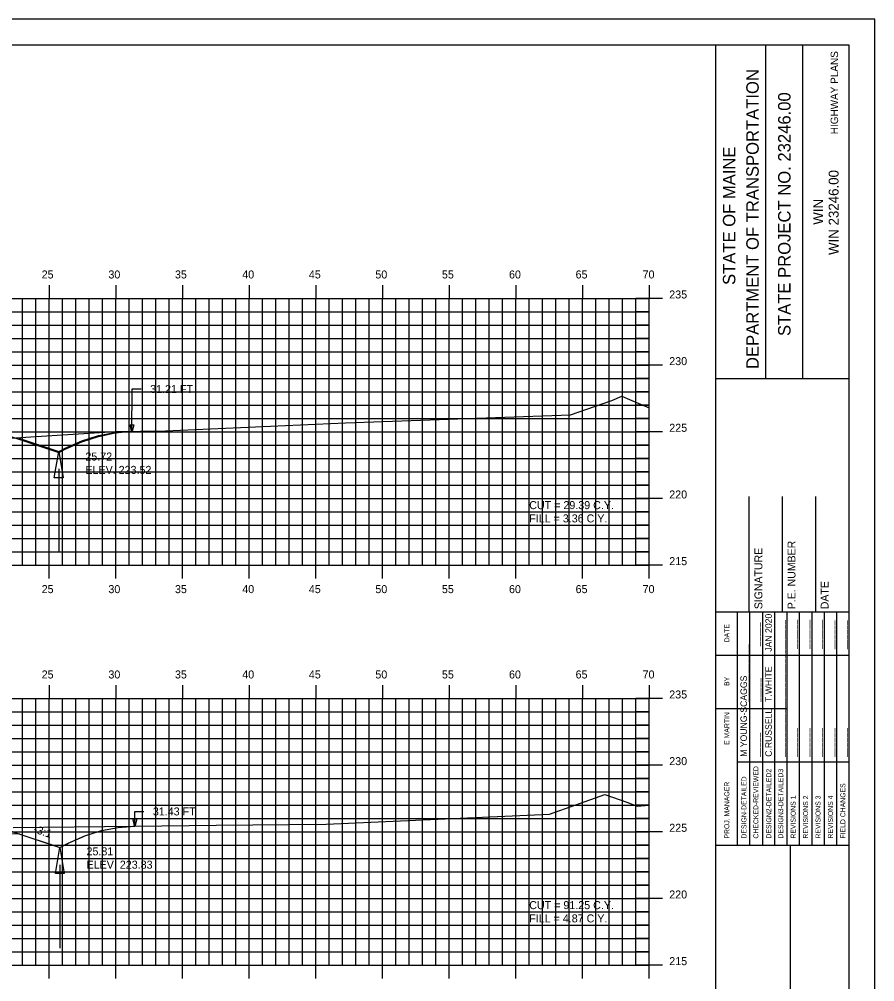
# Model space of a CAD drawing. Extents: x 1137433 to 1137603, y 608981 to 609091.
# Drawn here: x 1137538.4 to 1137602.6, y 609019.1 to 609091.3 of the extents above; entities that cross this region are included whole.
import ezdxf

# ---------------------------------------------------------------- set-up
doc = ezdxf.new("R2010")
doc.units = 0
for name, color, linetype in [('ANNOTATION', 7, 'Continuous'), ('BORDER', 7, 'Continuous'), ('D_Drainage_Ditch_Line', 7, 'Continuous'), ('D_Roadway_SlopeLines', 7, 'Continuous'), ('D_Roadway_SubGrade', 7, 'Continuous'), ('D_Text_Standard', 7, 'Continuous'), ('H_V ANNOTATION', 7, 'Continuous'), ('HIGHWAY_TITLE', 7, 'Continuous'), ('MAJOR', 7, 'Continuous'), ('MINOR', 7, 'Continuous'), ('PLOT BOUNDARY', 7, 'Continuous'), ('S_Roadway_Centerline', 7, 'Continuous')]:
    doc.layers.add(name, color=color, linetype=linetype)

msp = doc.modelspace()

# ---------------------------------------------------------------- linework, layer by layer
for points in [[(1137498.181, 609061.117), (1137500.653, 609061.475), (1137504.653, 609061.635), (1137515.653, 609062.075), (1137526.653, 609062.515), (1137530.653, 609062.355), (1137538.376, 609059.781), (1137541.376, 609058.781), (1137541.866, 609059.026), (1137543.116, 609059.579), (1137544.366, 609059.988), (1137545.616, 609060.252), (1137546.866, 609060.373)], [(1137537.514, 609030.485), (1137538.461, 609030.169), (1137541.099, 609029.29), (1137541.461, 609029.169), (1137542.009, 609029.443), (1137542.087, 609029.482), (1137543.187, 609029.965), (1137543.337, 609030.031), (1137544.437, 609030.379), (1137544.587, 609030.426), (1137545.687, 609030.639), (1137545.837, 609030.668), (1137546.937, 609030.747), (1137547.087, 609030.758)]]:
    msp.add_lwpolyline(points)
at = {"layer": 'BORDER'}
for p, q in [((1137590.653, 608984.335), (1137590.653, 609089.335)), ((1137594.382, 609064.332), (1137594.382, 609089.332)), ((1137597.177, 609064.332), (1137597.177, 609089.332)), ((1137590.654, 609064.329), (1137600.653, 609064.329)), ((1137593.153, 609046.838), (1137593.153, 609055.485)), ((1137595.653, 609046.838), (1137595.653, 609055.485)), ((1137598.153, 609046.838), (1137598.153, 609055.485)), ((1137590.653, 609046.838), (1137600.653, 609046.838)), ((1137590.653, 609029.338), (1137600.653, 609029.338)), ((1137596.244, 608994.338), (1137596.244, 609029.338))]:
    msp.add_line(p, q, dxfattribs=at)
msp.add_lwpolyline([(1137440.653, 608984.335), (1137600.653, 608984.335), (1137600.653, 609089.335), (1137440.653, 609089.335)], close=True, dxfattribs=at)
for points in [[(1137592.268, 609043.588), (1137592.268, 609046.838)], [(1137593.201, 609029.341), (1137593.201, 609046.838)], [(1137594.132, 609046.838), (1137594.132, 609029.341)], [(1137595.064, 609029.341), (1137595.064, 609046.838)], [(1137595.996, 609029.341), (1137595.996, 609046.838)], [(1137596.927, 609029.341), (1137596.927, 609046.838)], [(1137597.859, 609029.341), (1137597.859, 609046.838)], [(1137598.791, 609029.341), (1137598.791, 609046.838)], [(1137599.722, 609029.341), (1137599.722, 609046.838)], [(1137592.269, 609029.341), (1137592.269, 609046.132)], [(1137590.653, 609043.588), (1137600.653, 609043.588)], [(1137590.653, 609039.588), (1137592.269, 609039.588)], [(1137592.268, 609039.588), (1137595.995, 609039.588)], [(1137592.268, 609035.588), (1137600.653, 609035.588)]]:
    msp.add_lwpolyline(points, dxfattribs=at)
at = {"layer": 'D_Drainage_Ditch_Line'}
for p, q in [((1137541.376, 609057.549), (1137541.376, 609051.305)), ((1137541.461, 609027.857), (1137541.461, 609021.613))]:
    msp.add_line(p, q, dxfattribs=at)
for points in [[(1137541.704, 609056.892), (1137541.048, 609056.892), (1137541.376, 609058.861)], [(1137541.789, 609027.201), (1137541.133, 609027.201), (1137541.461, 609029.169)]]:
    msp.add_lwpolyline(points, close=True, dxfattribs=at)
at = {"layer": 'D_Roadway_SlopeLines'}
for points in [[(1137541.376, 609058.861), (1137541.866, 609059.106), (1137543.116, 609059.659), (1137544.366, 609060.068), (1137545.618, 609060.284), (1137546.863, 609060.373)], [(1137538.376, 609059.861), (1137541.376, 609058.861)], [(1137541.461, 609029.169), (1137542.087, 609029.482), (1137543.337, 609030.031), (1137544.587, 609030.426), (1137545.837, 609030.668), (1137547.087, 609030.758)], [(1137538.461, 609030.169), (1137541.461, 609029.169)]]:
    msp.add_lwpolyline(points, dxfattribs=at)
at = {"layer": 'D_Roadway_SubGrade'}
msp.add_lwpolyline([(1137526.653, 609032.489), (1137526.653, 609032.655), (1137530.653, 609032.522), (1137530.653, 609032.772), (1137530.653, 609032.772), (1137538.461, 609030.169), (1137526.653, 609030.405)], close=True, dxfattribs=at)
at = {"layer": 'D_Text_Standard'}
for points in [[(1137546.866, 609060.276), (1137546.874, 609063.546), (1137547.554, 609063.546)], [(1137547.087, 609030.732), (1137547.075, 609031.863), (1137547.755, 609031.863)]]:
    msp.add_lwpolyline(points, dxfattribs=at)
for points in [[(1137546.866, 609060.276), (1137546.722, 609060.858), (1137547.013, 609060.857)], [(1137547.087, 609030.732), (1137546.935, 609031.313), (1137547.226, 609031.316)]]:
    msp.add_lwpolyline(points, close=True, dxfattribs=at)
at = {"layer": 'MAJOR'}
for p, q in [((1137540.653, 609071.337), (1137540.653, 609070.335)), ((1137545.653, 609071.337), (1137545.653, 609070.335)), ((1137550.653, 609071.337), (1137550.653, 609070.335)), ((1137555.653, 609071.337), (1137555.653, 609070.335)), ((1137560.653, 609071.337), (1137560.653, 609070.335)), ((1137565.653, 609071.337), (1137565.653, 609070.335)), ((1137570.653, 609071.337), (1137570.653, 609070.335)), ((1137575.653, 609071.337), (1137575.653, 609070.335)), ((1137580.653, 609071.337), (1137580.653, 609070.335)), ((1137585.653, 609071.337), (1137585.653, 609070.335)), ((1137445.653, 609070.335), (1137585.653, 609070.335)), ((1137445.653, 609070.335), (1137585.653, 609070.335)), ((1137540.653, 609050.335), (1137540.653, 609070.335)), ((1137545.653, 609050.335), (1137545.653, 609070.335)), ((1137550.653, 609050.335), (1137550.653, 609070.335)), ((1137555.653, 609050.335), (1137555.653, 609070.335)), ((1137560.653, 609050.335), (1137560.653, 609070.335)), ((1137565.653, 609050.335), (1137565.653, 609070.335)), ((1137570.653, 609050.335), (1137570.653, 609070.335)), ((1137575.653, 609050.335), (1137575.653, 609070.335)), ((1137580.653, 609050.335), (1137580.653, 609070.335)), ((1137586.655, 609070.335), (1137584.651, 609070.335)), ((1137585.653, 609050.335), (1137585.653, 609070.335)), ((1137585.653, 609050.335), (1137585.653, 609070.335)), ((1137445.653, 609065.335), (1137585.653, 609065.335)), ((1137586.655, 609065.335), (1137584.651, 609065.335)), ((1137445.653, 609060.335), (1137585.653, 609060.335)), ((1137586.655, 609060.335), (1137584.651, 609060.335)), ((1137445.653, 609055.335), (1137585.653, 609055.335)), ((1137586.655, 609055.335), (1137584.651, 609055.335)), ((1137445.653, 609050.335), (1137585.653, 609050.335)), ((1137445.653, 609050.335), (1137585.653, 609050.335)), ((1137540.653, 609049.333), (1137540.653, 609050.335)), ((1137545.653, 609049.333), (1137545.653, 609050.335)), ((1137550.653, 609049.333), (1137550.653, 609050.335)), ((1137555.653, 609049.333), (1137555.653, 609050.335)), ((1137560.653, 609049.333), (1137560.653, 609050.335)), ((1137565.653, 609049.333), (1137565.653, 609050.335)), ((1137570.653, 609049.333), (1137570.653, 609050.335)), ((1137575.653, 609049.333), (1137575.653, 609050.335)), ((1137580.653, 609049.333), (1137580.653, 609050.335)), ((1137586.655, 609050.335), (1137584.651, 609050.335)), ((1137585.653, 609049.333), (1137585.653, 609050.335)), ((1137540.653, 609041.337), (1137540.653, 609040.335)), ((1137545.653, 609041.337), (1137545.653, 609040.335)), ((1137550.653, 609041.337), (1137550.653, 609040.335)), ((1137555.653, 609041.337), (1137555.653, 609040.335)), ((1137560.653, 609041.337), (1137560.653, 609040.335)), ((1137565.653, 609041.337), (1137565.653, 609040.335)), ((1137570.653, 609041.337), (1137570.653, 609040.335)), ((1137575.653, 609041.337), (1137575.653, 609040.335)), ((1137580.653, 609041.337), (1137580.653, 609040.335)), ((1137585.653, 609041.337), (1137585.653, 609040.335)), ((1137445.653, 609040.335), (1137585.653, 609040.335)), ((1137445.653, 609040.335), (1137585.653, 609040.335)), ((1137540.653, 609020.335), (1137540.653, 609040.335)), ((1137545.653, 609020.335), (1137545.653, 609040.335)), ((1137550.653, 609020.335), (1137550.653, 609040.335)), ((1137555.653, 609020.335), (1137555.653, 609040.335)), ((1137560.653, 609020.335), (1137560.653, 609040.335)), ((1137565.653, 609020.335), (1137565.653, 609040.335)), ((1137570.653, 609020.335), (1137570.653, 609040.335)), ((1137575.653, 609020.335), (1137575.653, 609040.335)), ((1137580.653, 609020.335), (1137580.653, 609040.335)), ((1137586.655, 609040.335), (1137584.651, 609040.335)), ((1137585.653, 609020.335), (1137585.653, 609040.335)), ((1137585.653, 609020.335), (1137585.653, 609040.335)), ((1137445.653, 609035.335), (1137585.653, 609035.335)), ((1137586.655, 609035.335), (1137584.651, 609035.335)), ((1137445.653, 609030.335), (1137585.653, 609030.335)), ((1137586.655, 609030.335), (1137584.651, 609030.335)), ((1137445.653, 609025.335), (1137585.653, 609025.335)), ((1137586.655, 609025.335), (1137584.651, 609025.335)), ((1137445.653, 609020.335), (1137585.653, 609020.335)), ((1137445.653, 609020.335), (1137585.653, 609020.335)), ((1137540.653, 609019.333), (1137540.653, 609020.335)), ((1137545.653, 609019.333), (1137545.653, 609020.335)), ((1137550.653, 609019.333), (1137550.653, 609020.335)), ((1137555.653, 609019.333), (1137555.653, 609020.335)), ((1137560.653, 609019.333), (1137560.653, 609020.335)), ((1137565.653, 609019.333), (1137565.653, 609020.335)), ((1137570.653, 609019.333), (1137570.653, 609020.335)), ((1137575.653, 609019.333), (1137575.653, 609020.335)), ((1137580.653, 609019.333), (1137580.653, 609020.335)), ((1137586.655, 609020.335), (1137584.651, 609020.335)), ((1137585.653, 609019.333), (1137585.653, 609020.335))]:
    msp.add_line(p, q, dxfattribs=at)
at = {"layer": 'MINOR'}
for p, q in [((1137538.653, 609050.335), (1137538.653, 609070.335)), ((1137539.653, 609050.335), (1137539.653, 609070.335)), ((1137541.653, 609050.335), (1137541.653, 609070.335)), ((1137542.653, 609050.335), (1137542.653, 609070.335)), ((1137543.653, 609050.335), (1137543.653, 609070.335)), ((1137544.653, 609050.335), (1137544.653, 609070.335)), ((1137546.653, 609050.335), (1137546.653, 609070.335)), ((1137547.653, 609050.335), (1137547.653, 609070.335)), ((1137548.653, 609050.335), (1137548.653, 609070.335)), ((1137549.653, 609050.335), (1137549.653, 609070.335)), ((1137551.653, 609050.335), (1137551.653, 609070.335)), ((1137552.653, 609050.335), (1137552.653, 609070.335)), ((1137553.653, 609050.335), (1137553.653, 609070.335)), ((1137554.653, 609050.335), (1137554.653, 609070.335)), ((1137556.653, 609050.335), (1137556.653, 609070.335)), ((1137557.653, 609050.335), (1137557.653, 609070.335)), ((1137558.653, 609050.335), (1137558.653, 609070.335)), ((1137559.653, 609050.335), (1137559.653, 609070.335)), ((1137561.653, 609050.335), (1137561.653, 609070.335)), ((1137562.653, 609050.335), (1137562.653, 609070.335)), ((1137563.653, 609050.335), (1137563.653, 609070.335)), ((1137564.653, 609050.335), (1137564.653, 609070.335)), ((1137566.653, 609050.335), (1137566.653, 609070.335)), ((1137567.653, 609050.335), (1137567.653, 609070.335)), ((1137568.653, 609050.335), (1137568.653, 609070.335)), ((1137569.653, 609050.335), (1137569.653, 609070.335)), ((1137571.653, 609050.335), (1137571.653, 609070.335)), ((1137572.653, 609050.335), (1137572.653, 609070.335)), ((1137573.653, 609050.335), (1137573.653, 609070.335)), ((1137574.653, 609050.335), (1137574.653, 609070.335)), ((1137576.653, 609050.335), (1137576.653, 609070.335)), ((1137577.653, 609050.335), (1137577.653, 609070.335)), ((1137578.653, 609050.335), (1137578.653, 609070.335)), ((1137579.653, 609050.335), (1137579.653, 609070.335)), ((1137581.653, 609050.335), (1137581.653, 609070.335)), ((1137582.653, 609050.335), (1137582.653, 609070.335)), ((1137583.653, 609050.335), (1137583.653, 609070.335)), ((1137584.653, 609050.335), (1137584.653, 609070.335)), ((1137445.653, 609069.335), (1137585.653, 609069.335)), ((1137585.653, 609069.335), (1137584.651, 609069.335)), ((1137445.653, 609068.335), (1137585.653, 609068.335)), ((1137585.653, 609068.335), (1137584.651, 609068.335)), ((1137445.653, 609067.335), (1137585.653, 609067.335)), ((1137585.653, 609067.335), (1137584.651, 609067.335)), ((1137445.653, 609066.335), (1137585.653, 609066.335)), ((1137585.653, 609066.335), (1137584.651, 609066.335)), ((1137445.653, 609064.335), (1137585.653, 609064.335)), ((1137585.653, 609064.335), (1137584.651, 609064.335)), ((1137445.653, 609063.335), (1137585.653, 609063.335)), ((1137585.653, 609063.335), (1137584.651, 609063.335)), ((1137445.653, 609062.335), (1137585.653, 609062.335)), ((1137585.653, 609062.335), (1137584.651, 609062.335)), ((1137445.653, 609061.335), (1137585.653, 609061.335)), ((1137585.653, 609061.335), (1137584.651, 609061.335)), ((1137445.653, 609059.335), (1137585.653, 609059.335)), ((1137585.653, 609059.335), (1137584.651, 609059.335)), ((1137445.653, 609058.335), (1137585.653, 609058.335)), ((1137585.653, 609058.335), (1137584.651, 609058.335)), ((1137445.653, 609057.335), (1137585.653, 609057.335)), ((1137585.653, 609057.335), (1137584.651, 609057.335)), ((1137445.653, 609056.335), (1137585.653, 609056.335)), ((1137585.653, 609056.335), (1137584.651, 609056.335)), ((1137445.653, 609054.335), (1137585.653, 609054.335)), ((1137585.653, 609054.335), (1137584.651, 609054.335)), ((1137445.653, 609053.335), (1137585.653, 609053.335)), ((1137585.653, 609053.335), (1137584.651, 609053.335)), ((1137445.653, 609052.335), (1137585.653, 609052.335)), ((1137585.653, 609052.335), (1137584.651, 609052.335)), ((1137445.653, 609051.335), (1137585.653, 609051.335)), ((1137585.653, 609051.335), (1137584.651, 609051.335)), ((1137538.653, 609020.335), (1137538.653, 609040.335)), ((1137539.653, 609020.335), (1137539.653, 609040.335)), ((1137541.653, 609020.335), (1137541.653, 609040.335)), ((1137542.653, 609020.335), (1137542.653, 609040.335)), ((1137543.653, 609020.335), (1137543.653, 609040.335)), ((1137544.653, 609020.335), (1137544.653, 609040.335)), ((1137546.653, 609020.335), (1137546.653, 609040.335)), ((1137547.653, 609020.335), (1137547.653, 609040.335)), ((1137548.653, 609020.335), (1137548.653, 609040.335)), ((1137549.653, 609020.335), (1137549.653, 609040.335)), ((1137551.653, 609020.335), (1137551.653, 609040.335)), ((1137552.653, 609020.335), (1137552.653, 609040.335)), ((1137553.653, 609020.335), (1137553.653, 609040.335)), ((1137554.653, 609020.335), (1137554.653, 609040.335)), ((1137556.653, 609020.335), (1137556.653, 609040.335)), ((1137557.653, 609020.335), (1137557.653, 609040.335)), ((1137558.653, 609020.335), (1137558.653, 609040.335)), ((1137559.653, 609020.335), (1137559.653, 609040.335)), ((1137561.653, 609020.335), (1137561.653, 609040.335)), ((1137562.653, 609020.335), (1137562.653, 609040.335)), ((1137563.653, 609020.335), (1137563.653, 609040.335)), ((1137564.653, 609020.335), (1137564.653, 609040.335)), ((1137566.653, 609020.335), (1137566.653, 609040.335)), ((1137567.653, 609020.335), (1137567.653, 609040.335)), ((1137568.653, 609020.335), (1137568.653, 609040.335)), ((1137569.653, 609020.335), (1137569.653, 609040.335)), ((1137571.653, 609020.335), (1137571.653, 609040.335)), ((1137572.653, 609020.335), (1137572.653, 609040.335)), ((1137573.653, 609020.335), (1137573.653, 609040.335)), ((1137574.653, 609020.335), (1137574.653, 609040.335)), ((1137576.653, 609020.335), (1137576.653, 609040.335)), ((1137577.653, 609020.335), (1137577.653, 609040.335)), ((1137578.653, 609020.335), (1137578.653, 609040.335)), ((1137579.653, 609020.335), (1137579.653, 609040.335)), ((1137581.653, 609020.335), (1137581.653, 609040.335)), ((1137582.653, 609020.335), (1137582.653, 609040.335)), ((1137583.653, 609020.335), (1137583.653, 609040.335)), ((1137584.653, 609020.335), (1137584.653, 609040.335)), ((1137445.653, 609039.335), (1137585.653, 609039.335)), ((1137585.653, 609039.335), (1137584.651, 609039.335)), ((1137445.653, 609038.335), (1137585.653, 609038.335)), ((1137585.653, 609038.335), (1137584.651, 609038.335)), ((1137445.653, 609037.335), (1137585.653, 609037.335)), ((1137585.653, 609037.335), (1137584.651, 609037.335)), ((1137445.653, 609036.335), (1137585.653, 609036.335)), ((1137585.653, 609036.335), (1137584.651, 609036.335)), ((1137445.653, 609034.335), (1137585.653, 609034.335)), ((1137585.653, 609034.335), (1137584.651, 609034.335)), ((1137445.653, 609033.335), (1137585.653, 609033.335)), ((1137585.653, 609033.335), (1137584.651, 609033.335)), ((1137445.653, 609032.335), (1137585.653, 609032.335)), ((1137585.653, 609032.335), (1137584.651, 609032.335)), ((1137445.653, 609031.335), (1137585.653, 609031.335)), ((1137585.653, 609031.335), (1137584.651, 609031.335)), ((1137445.653, 609029.335), (1137585.653, 609029.335)), ((1137585.653, 609029.335), (1137584.651, 609029.335)), ((1137445.653, 609028.335), (1137585.653, 609028.335)), ((1137585.653, 609028.335), (1137584.651, 609028.335)), ((1137445.653, 609027.335), (1137585.653, 609027.335)), ((1137585.653, 609027.335), (1137584.651, 609027.335)), ((1137445.653, 609026.335), (1137585.653, 609026.335)), ((1137585.653, 609026.335), (1137584.651, 609026.335)), ((1137445.653, 609024.335), (1137585.653, 609024.335)), ((1137585.653, 609024.335), (1137584.651, 609024.335)), ((1137445.653, 609023.335), (1137585.653, 609023.335)), ((1137585.653, 609023.335), (1137584.651, 609023.335)), ((1137445.653, 609022.335), (1137585.653, 609022.335)), ((1137585.653, 609022.335), (1137584.651, 609022.335)), ((1137445.653, 609021.335), (1137585.653, 609021.335)), ((1137585.653, 609021.335), (1137584.651, 609021.335))]:
    msp.add_line(p, q, dxfattribs=at)
at = {"layer": 'PLOT BOUNDARY'}
msp.add_lwpolyline([(1137432.56, 608981.276), (1137602.56, 608981.276), (1137602.56, 609091.276), (1137432.56, 609091.276)], close=True, dxfattribs=at)
at = {"layer": 'S_Roadway_Centerline'}
for points in [[(1137535.521, 609059.696), (1137539.278, 609059.952), (1137545.626, 609060.356), (1137549.392, 609060.408), (1137562.884, 609061.019), (1137579.739, 609061.615), (1137582.845, 609062.69), (1137583.593, 609063.018), (1137584.161, 609062.745), (1137585.653, 609062.139)], [(1137537.95, 609030.665), (1137547.085, 609030.758), (1137553.194, 609030.832), (1137561.442, 609030.911), (1137578.167, 609031.657), (1137580.151, 609032.348), (1137582.312, 609033.134), (1137583.962, 609032.568), (1137584.735, 609032.265), (1137585.653, 609032.338)]]:
    msp.add_lwpolyline(points, dxfattribs=at)

# ---------------------------------------------------------------- texts
at = {"layer": 'ANNOTATION'}
msp.add_text('-3:1', height=0.6, rotation=341.56517, dxfattribs=at).set_placement((1137539.43, 609030.3))
at = {"layer": 'BORDER'}
for s, height, p in [('DEPARTMENT OF TRANSPORTATION', 0.93176, (1137593.86, 609065.041)), ('STATE PROJECT NO. 23246.00', 0.93176, (1137596.245, 609067.517)), ('STATE OF MAINE', 0.93176, (1137592.108, 609071.347)), ('WIN 23246.00', 0.74527, (1137599.849, 609073.596)), ('WIN', 0.7453, (1137598.69, 609075.865)), ('SIGNATURE', 0.5906, (1137594.134, 609047.03)), ('P.E. NUMBER', 0.59055, (1137596.614, 609047.03)), ('DATE', 0.5906, (1137599.094, 609047.03)), ('JAN 2020', 0.4845, (1137594.839, 609043.843)), ('DATE', 0.3714, (1137591.657, 609044.544)), ('_____', 0.4845, (1137593.87, 609044.243)), ('______', 0.4845, (1137595.734, 609044.063)), ('______', 0.4845, (1137596.665, 609044.065)), ('______', 0.4845, (1137597.597, 609044.067)), ('______', 0.4845, (1137598.529, 609044.067)), ('______', 0.4845, (1137599.461, 609044.036)), ('______', 0.4845, (1137600.392, 609044.036)), ('____________', 0.48455, (1137592.976, 609040.073)), ('____________', 0.48455, (1137595.734, 609040.073)), ('T.WHITE', 0.4845, (1137594.839, 609040.073)), ('BY', 0.3714, (1137591.657, 609041.273)), ('M YOUNG-SCAGGS', 0.48455, (1137592.976, 609035.961)), ('_____', 0.4845, (1137593.908, 609040.073)), ('____________', 0.48455, (1137595.734, 609035.961)), ('C.RUSSELL', 0.4845, (1137594.839, 609035.961)), ('E MARTIN', 0.3727, (1137591.657, 609036.855)), ('_____', 0.4845, (1137593.87, 609035.961)), ('______', 0.4845, (1137596.665, 609035.961)), ('______', 0.4845, (1137597.597, 609035.961)), ('______', 0.4845, (1137598.529, 609035.961)), ('______', 0.4845, (1137599.461, 609035.961)), ('______', 0.4845, (1137600.392, 609035.961)), ('CHECKED-REVIEWED', 0.37275, (1137593.834, 609029.826)), ('DESIGN2-DETAILED2', 0.37275, (1137594.803, 609029.826)), ('DESIGN3-DETAILED3', 0.37275, (1137595.697, 609029.826)), ('DESIGN-DETAILED', 0.37275, (1137592.94, 609029.826)), ('PROJ. MANAGER', 0.37275, (1137591.657, 609029.826)), ('FIELD CHANGES', 0.37275, (1137600.356, 609029.826)), ('REVISIONS 1', 0.37275, (1137596.629, 609029.826)), ('REVISIONS 2', 0.37275, (1137597.561, 609029.826)), ('REVISIONS 3', 0.37275, (1137598.492, 609029.826)), ('REVISIONS 4', 0.37275, (1137599.424, 609029.826))]:
    msp.add_text(s, height=height, rotation=90, dxfattribs=at).set_placement(p)
at = {"layer": 'D_Text_Standard'}
for s, p in [('31.21 FT', (1137548.234, 609063.246)), ('25.72', (1137543.376, 609058.181)), ('ELEV. 223.52', (1137543.376, 609057.179)), ('CUT = 29.39 C.Y.', (1137576.653, 609054.535)), ('FILL = 3.36 C.Y.', (1137576.653, 609053.539)), ('31.43 FT', (1137548.435, 609031.563)), ('25.81', (1137543.461, 609028.569)), ('ELEV. 223.83', (1137543.461, 609027.567)), ('CUT = 91.25 C.Y.', (1137576.653, 609024.535)), ('FILL = 4.87 C.Y.', (1137576.653, 609023.539))]:
    msp.add_text(s, height=0.6, dxfattribs=at).set_placement(p)
at = {"layer": 'H_V ANNOTATION'}
for s, p in [('25', (1137540.099, 609071.835)), ('30', (1137545.102, 609071.835)), ('35', (1137550.094, 609071.835)), ('40', (1137555.139, 609071.835)), ('45', (1137560.131, 609071.835)), ('50', (1137565.118, 609071.835)), ('55', (1137570.11, 609071.835)), ('60', (1137575.139, 609071.835)), ('65', (1137580.131, 609071.835)), ('70', (1137585.155, 609071.835)), ('235', (1137587.153, 609070.335)), ('230', (1137587.153, 609065.335)), ('225', (1137587.153, 609060.335)), ('220', (1137587.153, 609055.335)), ('215', (1137587.153, 609050.335)), ('25', (1137540.099, 609048.235)), ('30', (1137545.102, 609048.235)), ('35', (1137550.094, 609048.235)), ('40', (1137555.139, 609048.235)), ('45', (1137560.131, 609048.235)), ('50', (1137565.118, 609048.235)), ('55', (1137570.11, 609048.235)), ('60', (1137575.139, 609048.235)), ('65', (1137580.131, 609048.235)), ('70', (1137585.155, 609048.235)), ('25', (1137540.099, 609041.835)), ('30', (1137545.102, 609041.835)), ('35', (1137550.094, 609041.835)), ('40', (1137555.139, 609041.835)), ('45', (1137560.131, 609041.835)), ('50', (1137565.118, 609041.835)), ('55', (1137570.11, 609041.835)), ('60', (1137575.139, 609041.835)), ('65', (1137580.131, 609041.835)), ('70', (1137585.155, 609041.835)), ('235', (1137587.153, 609040.335)), ('230', (1137587.153, 609035.335)), ('225', (1137587.153, 609030.335)), ('220', (1137587.153, 609025.335)), ('215', (1137587.153, 609020.335))]:
    msp.add_text(s, height=0.6, dxfattribs=at).set_placement(p)
at = {"layer": 'HIGHWAY_TITLE'}
msp.add_text('HIGHWAY PLANS', height=0.55901, rotation=90, dxfattribs=at).set_placement((1137599.811, 609082.65))

doc.saveas('drawing.dxf')
